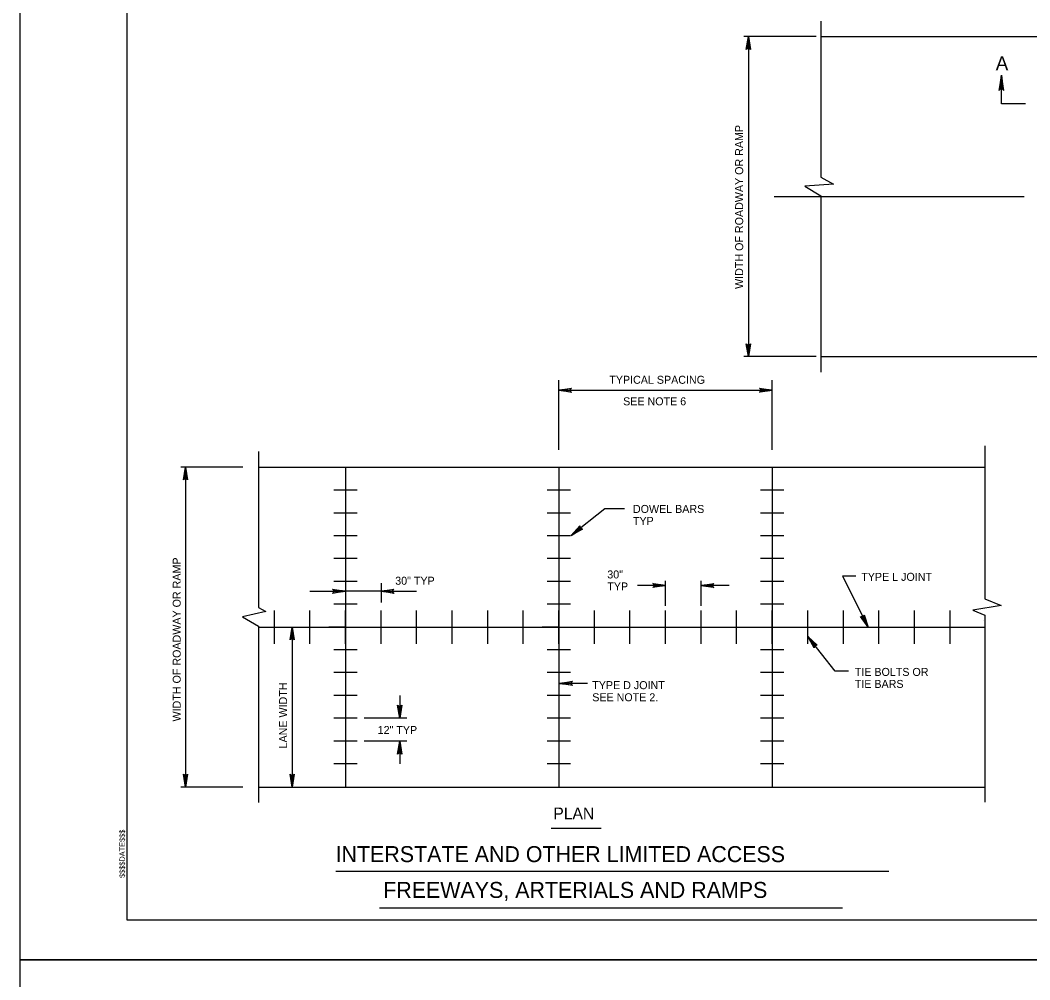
# Model space of a CAD drawing. Extents: x 637877 to 639321, y 297902 to 299090.
# Drawn here: x 638415.5 to 638794.1, y 298488.1 to 298847.9 of the extents above; entities that cross this region are included whole.
import ezdxf

# ---------------------------------------------------------------- set-up
doc = ezdxf.new("R2010")
doc.units = 0
for name, color, linetype in [('1', 7, 'Continuous'), ('2', 7, 'Continuous'), ('3', 7, 'Continuous'), ('PLT-BNDY', 7, 'Continuous')]:
    doc.layers.add(name, color=color, linetype=linetype)

msp = doc.modelspace()

# ---------------------------------------------------------------- linework, layer by layer
at = {"layer": '1'}
for points in [[(639241.51, 298510.57), (639241.51, 299074.57), (638455.51, 299074.57), (638455.51, 298510.57), (639241.51, 298510.57), (639241.51, 298536.93), (639041.51, 298536.93), (639041.51, 298601.61), (639241.51, 298601.61), (639241.51, 298630.57), (639041.51, 298630.57), (639041.51, 298510.57), (639120.32, 298510.57), (639120.32, 298536.93), (639120.32, 298510.57), (639197.32, 298510.57), (639197.32, 298536.93), (639197.32, 298524.61), (639241.51, 298524.61)], [(638626.05, 298657.15), (638625.71, 298657.3), (638622.08, 298654.74), (638626.05, 298657.15), (638626.37, 298657.13), (638622.08, 298654.74), (638625.42, 298657.66), (638625.34, 298658.02), (638622.08, 298654.74), (638625.4, 298658.35), (638625.34, 298658.02)], [(638532.86, 298634.34), (638533.03, 298634.01), (638537.47, 298633.76), (638532.86, 298634.34), (638532.62, 298634.54), (638537.47, 298633.76), (638533.03, 298633.54), (638532.87, 298633.21), (638537.47, 298633.76), (638532.62, 298632.99), (638532.87, 298633.21)], [(638555.42, 298633.18), (638555.25, 298633.52), (638550.81, 298633.76), (638555.42, 298633.18), (638555.65, 298632.98), (638550.81, 298633.76), (638555.24, 298633.98), (638555.4, 298634.31), (638550.81, 298633.76), (638555.65, 298634.53), (638555.4, 298634.31)], [(638622.37, 298598.67), (638622.2, 298599.01), (638617.75, 298599.25), (638622.37, 298598.67), (638622.6, 298598.47), (638617.75, 298599.25), (638622.19, 298599.47), (638622.35, 298599.8), (638617.75, 298599.25), (638622.6, 298600.02), (638622.35, 298599.8)], [(638558.38, 298590.77), (638558.04, 298590.6), (638557.8, 298586.16), (638558.38, 298590.77), (638558.58, 298591.01), (638557.8, 298586.16), (638557.58, 298590.59), (638557.25, 298590.76), (638557.8, 298586.16), (638557.03, 298591.01), (638557.25, 298590.76)], [(638557.22, 298572.99), (638557.55, 298573.16), (638557.8, 298577.6), (638557.22, 298572.99), (638557.02, 298572.75), (638557.8, 298577.6), (638558.02, 298573.17), (638558.35, 298573), (638557.8, 298577.6), (638558.57, 298572.75), (638558.35, 298573)]]:
    msp.add_lwpolyline(points, dxfattribs=at)
at = {"layer": '2'}
for p, q in [((638715.64, 298847.57), (638715.64, 298789.06)), ((638713.89, 298841.76), (638686.77, 298841.76)), ((638688.52, 298841.76), (638688.52, 298721.76)), ((638715.64, 298841.76), (638990.64, 298841.76)), ((638698.18, 298781.76), (638791.89, 298781.76)), ((638715.64, 298782.1), (638715.64, 298716)), ((638713.89, 298721.76), (638686.77, 298721.76)), ((638715.64, 298721.76), (638990.64, 298721.76)), ((638717.39, 298721.76), (638731.08, 298721.76)), ((638617.47, 298686.84), (638617.47, 298712.97)), ((638697.47, 298686.84), (638697.47, 298712.97)), ((638617.47, 298709.15), (638697.47, 298709.15)), ((638504.87, 298686.17), (638504.87, 298627.66)), ((638777.16, 298688.37), (638777.16, 298630.88)), ((638499.03, 298680.36), (638475.77, 298680.36)), ((638477.52, 298680.36), (638477.52, 298560.36)), ((638504.87, 298680.36), (638777.16, 298680.36)), ((638537.47, 298680.36), (638537.47, 298560.36)), ((638617.47, 298680.36), (638617.47, 298560.36)), ((638697.47, 298680.36), (638697.47, 298560.36)), ((638634.67, 298664.7), (638622.08, 298654.74)), ((638642.1, 298664.7), (638634.67, 298664.7)), ((638550.81, 298636.76), (638550.81, 298629.57)), ((638657.47, 298635.94), (638646.97, 298635.94)), ((638657.47, 298628.36), (638657.47, 298637.69)), ((638670.81, 298628.36), (638670.81, 298637.69)), ((638681.31, 298635.94), (638670.81, 298635.94)), ((638524.14, 298633.76), (638537.47, 298633.76)), ((638550.81, 298633.76), (638537.47, 298633.76)), ((638550.81, 298633.76), (638564.14, 298633.76)), ((638777.16, 298624.85), (638777.16, 298554.68)), ((638504.87, 298620.7), (638504.87, 298554.6)), ((638776.7, 298622.84), (638776.7, 298622.84)), ((638776.7, 298622.84), (638776.7, 298622.84)), ((638776.7, 298622.84), (638776.7, 298622.84)), ((638776.7, 298622.84), (638776.7, 298622.84)), ((638776.7, 298622.84), (638776.7, 298622.84)), ((638776.7, 298622.84), (638776.7, 298622.84)), ((638776.7, 298622.84), (638776.7, 298622.84)), ((638776.7, 298622.84), (638776.7, 298622.84)), ((638776.7, 298622.84), (638776.7, 298622.84)), ((638776.7, 298622.84), (638776.7, 298622.84)), ((638776.7, 298622.84), (638776.7, 298622.84)), ((638504.87, 298620.36), (638777.16, 298620.36)), ((638509.6, 298620.36), (638509.88, 298620.36)), ((638510.81, 298620.36), (638510.81, 298620.36)), ((638517.47, 298620.36), (638517.47, 298560.36)), ((638517.47, 298620.36), (638517.47, 298620.36)), ((638518.32, 298620.36), (638518.32, 298620.36)), ((638530.81, 298620.36), (638530.81, 298620.36)), ((638537.47, 298620.36), (638537.47, 298620.36)), ((638544.14, 298620.36), (638544.14, 298620.36)), ((638544.14, 298620.36), (638544.14, 298620.36)), ((638544.14, 298620.36), (638544.14, 298620.36)), ((638544.14, 298620.36), (638544.14, 298620.36)), ((638544.14, 298620.36), (638544.14, 298620.36)), ((638550.81, 298620.36), (638550.81, 298620.36)), ((638557.47, 298620.36), (638557.47, 298620.36)), ((638564.14, 298620.36), (638564.14, 298620.36)), ((638570.81, 298620.36), (638570.81, 298620.36)), ((638577.47, 298620.36), (638577.47, 298620.36)), ((638584.14, 298620.36), (638584.14, 298620.36)), ((638590.81, 298620.36), (638590.81, 298620.36)), ((638597.47, 298620.36), (638597.47, 298620.36)), ((638604.14, 298620.36), (638604.14, 298620.36)), ((638610.81, 298620.36), (638610.81, 298620.36)), ((638617.47, 298620.36), (638617.47, 298620.36)), ((638624.14, 298620.36), (638624.14, 298620.36)), ((638624.14, 298620.36), (638624.14, 298620.36)), ((638624.14, 298620.36), (638624.14, 298620.36)), ((638624.14, 298620.36), (638624.14, 298620.36)), ((638624.14, 298620.36), (638624.14, 298620.36)), ((638630.81, 298620.36), (638630.81, 298620.36)), ((638637.47, 298620.36), (638637.47, 298620.36)), ((638644.14, 298620.36), (638644.14, 298620.36)), ((638650.81, 298620.36), (638650.81, 298620.36)), ((638657.47, 298620.36), (638657.47, 298620.36)), ((638664.14, 298620.36), (638664.14, 298620.36)), ((638670.81, 298620.36), (638670.81, 298620.36)), ((638677.47, 298620.36), (638677.47, 298620.36)), ((638684.14, 298620.36), (638684.14, 298620.36)), ((638697.47, 298620.36), (638697.47, 298620.36)), ((638704.14, 298620.36), (638704.14, 298620.36)), ((638704.14, 298620.36), (638704.14, 298620.36)), ((638704.14, 298620.36), (638704.14, 298620.36)), ((638704.14, 298620.36), (638704.14, 298620.36)), ((638704.14, 298620.36), (638704.14, 298620.36)), ((638710.81, 298620.36), (638710.81, 298620.36)), ((638717.47, 298620.36), (638717.47, 298620.36)), ((638724.14, 298620.36), (638724.14, 298620.36)), ((638730.81, 298620.36), (638730.81, 298620.36)), ((638737.47, 298620.36), (638737.47, 298620.36)), ((638744.14, 298620.36), (638744.14, 298620.36)), ((638750.81, 298620.36), (638750.81, 298620.36)), ((638757.47, 298620.36), (638757.47, 298620.36)), ((638764.14, 298620.36), (638764.14, 298620.36)), ((638628.25, 298599.25), (638617.75, 298599.25)), ((638557.8, 298594.71), (638557.8, 298586.16)), ((638560.46, 298586.16), (638544.48, 298586.16)), ((638560.46, 298577.6), (638544.48, 298577.6)), ((638557.8, 298577.6), (638557.8, 298569.05)), ((638499.03, 298560.36), (638475.77, 298560.36)), ((638504.87, 298560.36), (638777.16, 298560.36)), ((638511.35, 298560.36), (638525.04, 298560.36))]:
    msp.add_line(p, q, dxfattribs=at)
for points in [[(638687.95, 298837.22), (638688.28, 298837.39), (638688.52, 298841.76), (638687.95, 298837.22), (638687.75, 298836.99), (638688.52, 298841.76), (638688.73, 298837.4), (638689.06, 298837.24), (638688.52, 298841.76), (638689.28, 298836.99), (638689.06, 298837.24)], [(638784.07, 298821.86), (638783.67, 298822.06), (638783.38, 298827.31), (638784.07, 298821.86), (638784.31, 298821.58), (638783.38, 298827.31), (638783.12, 298822.07), (638782.73, 298821.87), (638783.38, 298827.31), (638782.47, 298821.58), (638782.73, 298821.87)], [(638792.38, 298816.51), (638783.38, 298816.51), (638783.38, 298827.31)], [(638715.64, 298789.06), (638720.48, 298786.5), (638709.64, 298785.64), (638715.64, 298782.1)], [(638689.09, 298726.3), (638688.76, 298726.14), (638688.52, 298721.76), (638689.09, 298726.3), (638689.29, 298726.54), (638688.52, 298721.76), (638688.3, 298726.13), (638687.98, 298726.29), (638688.52, 298721.76), (638687.76, 298726.54), (638687.98, 298726.29)], [(638622.01, 298708.58), (638621.84, 298708.91), (638617.47, 298709.15), (638622.01, 298708.58), (638622.25, 298708.38), (638617.47, 298709.15), (638621.84, 298709.37), (638622, 298709.69), (638617.47, 298709.15), (638622.25, 298709.91), (638622, 298709.69)], [(638692.93, 298709.72), (638693.1, 298709.39), (638697.47, 298709.15), (638692.93, 298709.72), (638692.7, 298709.92), (638697.47, 298709.15), (638693.1, 298708.93), (638692.94, 298708.61), (638697.47, 298709.15), (638692.7, 298708.39), (638692.94, 298708.61)], [(638476.95, 298675.82), (638477.28, 298675.99), (638477.52, 298680.36), (638476.95, 298675.82), (638476.75, 298675.59), (638477.52, 298680.36), (638477.74, 298676), (638478.06, 298675.84), (638477.52, 298680.36), (638478.28, 298675.59), (638478.06, 298675.84)], [(638541.86, 298671.67), (638533.08, 298671.67)], [(638621.86, 298671.67), (638613.08, 298671.67)], [(638701.86, 298671.67), (638693.08, 298671.67)], [(638541.86, 298663.12), (638537.47, 298663.12), (638533.08, 298663.12)], [(638621.86, 298663.12), (638617.47, 298663.12), (638613.08, 298663.12)], [(638701.86, 298663.12), (638697.47, 298663.12), (638693.08, 298663.12)], [(638541.86, 298654.57), (638533.08, 298654.57)], [(638621.86, 298654.57), (638613.08, 298654.57)], [(638701.86, 298654.57), (638693.08, 298654.57)], [(638541.86, 298646.02), (638537.47, 298646.02), (638533.08, 298646.02)], [(638621.86, 298646.02), (638617.47, 298646.02), (638613.08, 298646.02)], [(638701.86, 298646.02), (638697.47, 298646.02), (638693.08, 298646.02)], [(638728.83, 298639.42), (638723.83, 298639.42), (638733.4, 298620.36)], [(638541.86, 298637.47), (638533.08, 298637.47)], [(638621.86, 298637.47), (638613.08, 298637.47)], [(638652.93, 298636.51), (638653.1, 298636.18), (638657.47, 298635.94), (638652.93, 298636.51), (638652.7, 298636.71), (638657.47, 298635.94), (638653.1, 298635.73), (638652.94, 298635.4), (638657.47, 298635.94), (638652.7, 298635.18), (638652.94, 298635.4)], [(638675.35, 298635.37), (638675.18, 298635.7), (638670.81, 298635.94), (638675.35, 298635.37), (638675.58, 298635.17), (638670.81, 298635.94), (638675.17, 298636.16), (638675.33, 298636.48), (638670.81, 298635.94), (638675.58, 298636.7), (638675.33, 298636.48)], [(638701.86, 298637.47), (638693.08, 298637.47)], [(638541.86, 298628.92), (638537.47, 298628.92), (638533.08, 298628.92)], [(638621.86, 298628.92), (638617.47, 298628.92), (638613.08, 298628.92)], [(638701.86, 298628.92), (638697.47, 298628.92), (638693.08, 298628.92)], [(638777.16, 298630.88), (638783.28, 298628.43), (638772.72, 298626.72), (638777.16, 298624.85)], [(638504.87, 298627.66), (638507.64, 298626.17), (638498.88, 298624.24), (638504.87, 298620.7)], [(638510.81, 298614.11), (638510.81, 298620.36), (638510.81, 298626.61)], [(638524.14, 298614.11), (638524.14, 298620.36), (638524.14, 298626.61)], [(638537.47, 298614.11), (638537.47, 298620.36), (638537.47, 298626.61)], [(638550.81, 298614.11), (638550.81, 298620.36), (638550.81, 298626.61)], [(638564.14, 298614.11), (638564.14, 298620.36), (638564.14, 298626.61)], [(638577.47, 298614.11), (638577.47, 298620.36), (638577.47, 298626.61)], [(638590.81, 298614.11), (638590.81, 298620.36), (638590.81, 298626.61)], [(638604.14, 298614.11), (638604.14, 298620.36), (638604.14, 298626.61)], [(638617.47, 298614.11), (638617.47, 298620.36), (638617.47, 298626.61)], [(638630.81, 298614.11), (638630.81, 298620.36), (638630.81, 298626.61)], [(638644.14, 298614.11), (638644.14, 298620.36), (638644.14, 298626.61)], [(638657.47, 298614.11), (638657.47, 298620.36), (638657.47, 298626.61)], [(638670.81, 298614.11), (638670.81, 298620.36), (638670.81, 298626.61)], [(638684.14, 298614.11), (638684.14, 298620.36), (638684.14, 298626.61)], [(638697.47, 298614.11), (638697.47, 298620.36), (638697.47, 298626.61)], [(638710.81, 298614.11), (638710.81, 298620.36), (638710.81, 298626.61)], [(638724.14, 298614.11), (638724.14, 298620.36), (638724.14, 298626.61)], [(638731.87, 298624.68), (638731.65, 298624.38), (638733.4, 298620.36), (638731.87, 298624.68), (638731.94, 298624.98), (638733.4, 298620.36), (638731.24, 298624.17), (638730.88, 298624.17), (638733.4, 298620.36), (638730.58, 298624.29), (638730.88, 298624.17)], [(638737.47, 298614.11), (638737.47, 298620.36), (638737.47, 298626.61)], [(638750.81, 298614.11), (638750.81, 298620.36), (638750.81, 298626.61)], [(638764.14, 298614.11), (638764.14, 298620.36), (638764.14, 298626.61)], [(638516.9, 298615.82), (638517.23, 298615.99), (638517.47, 298620.36), (638516.9, 298615.82), (638516.7, 298615.59), (638517.47, 298620.36), (638517.69, 298616), (638518.01, 298615.84), (638517.47, 298620.36), (638518.23, 298615.59), (638518.01, 298615.84)], [(638537.47, 298620.36), (638531.22, 298620.36)], [(638617.47, 298620.36), (638611.22, 298620.36)], [(638726.03, 298603.84), (638721.03, 298603.84), (638710.81, 298616.8)], [(638713.17, 298612.88), (638713.32, 298613.22), (638710.81, 298616.8), (638713.17, 298612.88), (638713.16, 298612.58), (638710.81, 298616.8), (638713.68, 298613.5), (638714.03, 298613.58), (638710.81, 298616.8), (638714.36, 298613.52), (638714.03, 298613.58)], [(638541.86, 298611.81), (638537.47, 298611.81), (638533.08, 298611.81)], [(638621.86, 298611.81), (638617.47, 298611.81), (638613.08, 298611.81)], [(638701.86, 298611.81), (638697.47, 298611.81), (638693.08, 298611.81)], [(638541.86, 298603.26), (638533.08, 298603.26)], [(638621.86, 298603.26), (638613.08, 298603.26)], [(638701.86, 298603.26), (638693.08, 298603.26)], [(638541.86, 298594.71), (638537.47, 298594.71), (638533.08, 298594.71)], [(638621.86, 298594.71), (638617.47, 298594.71), (638613.08, 298594.71)], [(638701.86, 298594.71), (638697.47, 298594.71), (638693.08, 298594.71)], [(638541.86, 298586.16), (638533.08, 298586.16)], [(638621.86, 298586.16), (638613.08, 298586.16)], [(638701.86, 298586.16), (638693.08, 298586.16)], [(638541.86, 298577.6), (638537.47, 298577.6), (638533.08, 298577.6)], [(638621.86, 298577.6), (638617.47, 298577.6), (638613.08, 298577.6)], [(638701.86, 298577.6), (638697.47, 298577.6), (638693.08, 298577.6)], [(638541.86, 298569.05), (638533.08, 298569.05)], [(638621.86, 298569.05), (638613.08, 298569.05)], [(638701.86, 298569.05), (638693.08, 298569.05)], [(638478.09, 298564.91), (638477.76, 298564.74), (638477.52, 298560.36), (638478.09, 298564.91), (638478.29, 298565.14), (638477.52, 298560.36), (638477.31, 298564.73), (638476.98, 298564.89), (638477.52, 298560.36), (638476.76, 298565.14), (638476.98, 298564.89)], [(638518.04, 298564.91), (638517.71, 298564.74), (638517.47, 298560.36), (638518.04, 298564.91), (638518.24, 298565.14), (638517.47, 298560.36), (638517.26, 298564.73), (638516.93, 298564.89), (638517.47, 298560.36), (638516.71, 298565.14), (638516.93, 298564.89)]]:
    msp.add_lwpolyline(points, dxfattribs=at)
at = {"layer": '3'}
for p, q in [((638614.62, 298544.89), (638633.35, 298544.89)), ((638533.8, 298528.82), (638741.16, 298528.82)), ((638550.19, 298515.07), (638723.78, 298515.07))]:
    msp.add_line(p, q, dxfattribs=at)
at = {"layer": 'PLT-BNDY'}
for points in [[(638415.51, 299089.57), (639256.51, 299089.57), (639256.51, 298495.57), (638415.51, 298495.57)], [(638415.51, 298495.57), (639256.51, 298495.57), (639256.51, 297901.57), (638415.51, 297901.57)]]:
    msp.add_lwpolyline(points, close=True, dxfattribs=at)

# ---------------------------------------------------------------- texts
at = {"layer": '1'}
msp.add_text('$$$$DATE$$$', height=2, rotation=90, dxfattribs=at).set_placement((638454.73, 298526.26))
at = {"layer": '2'}
for s, height, p in [('SEE NOTE 6', 3, (638641.57, 298703.51)), ('DOWEL BARS', 2.999, (638645.25, 298663.15)), ('TYP', 2.999, (638645.25, 298658.65)), ('30"', 2.999, (638635.64, 298638.59)), ('TYP', 2.999, (638635.64, 298634.09))]:
    msp.add_text(s, height=height, dxfattribs=at).set_placement(p)
at = {"layer": '3'}
for s, height, p in [('A', 5.25, (638781.28, 298829.18)), ('TYPICAL SPACING', 2.9995, (638636.39, 298711.59)), ('TYPE L JOINT', 2.9995, (638730.86, 298637.69)), ('30" TYP', 3, (638556.12, 298636.23)), ('TIE BOLTS OR', 2.9995, (638728.43, 298602.03)), ('TYPE D JOINT', 2.9995, (638630, 298597.07)), ('TIE BARS', 2.999, (638728.43, 298597.53)), ('SEE NOTE 2.', 2.9995, (638630, 298592.53)), ('12" TYP', 3, (638549.54, 298580.26)), ('PLAN', 4.375, (638615.43, 298548.29)), ('INTERSTATE AND OTHER LIMITED ACCESS', 6, (638533.77, 298532.21)), ('FREEWAYS, ARTERIALS AND RAMPS', 6, (638551.63, 298518.78))]:
    msp.add_text(s, height=height, dxfattribs=at).set_placement(p)
for s, height, p in [('WIDTH OF ROADWAY OR RAMP', 2.9995, (638686.58, 298747.16)), ('WIDTH OF ROADWAY OR RAMP', 2.9995, (638475.7, 298584.95)), ('LANE WIDTH', 2.999, (638515.58, 298574.84))]:
    msp.add_text(s, height=height, rotation=90, dxfattribs=at).set_placement(p)

doc.saveas('drawing.dxf')
